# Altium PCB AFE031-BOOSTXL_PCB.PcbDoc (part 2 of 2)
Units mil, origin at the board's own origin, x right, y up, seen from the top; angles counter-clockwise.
Board outline 2300 x 2000 mil, 4 copper layers (Top Layer, POWER, GND, Bottom Layer), stack 61.6 mil thick; 92 components, 52 nets, 268 pads, 81 vias.
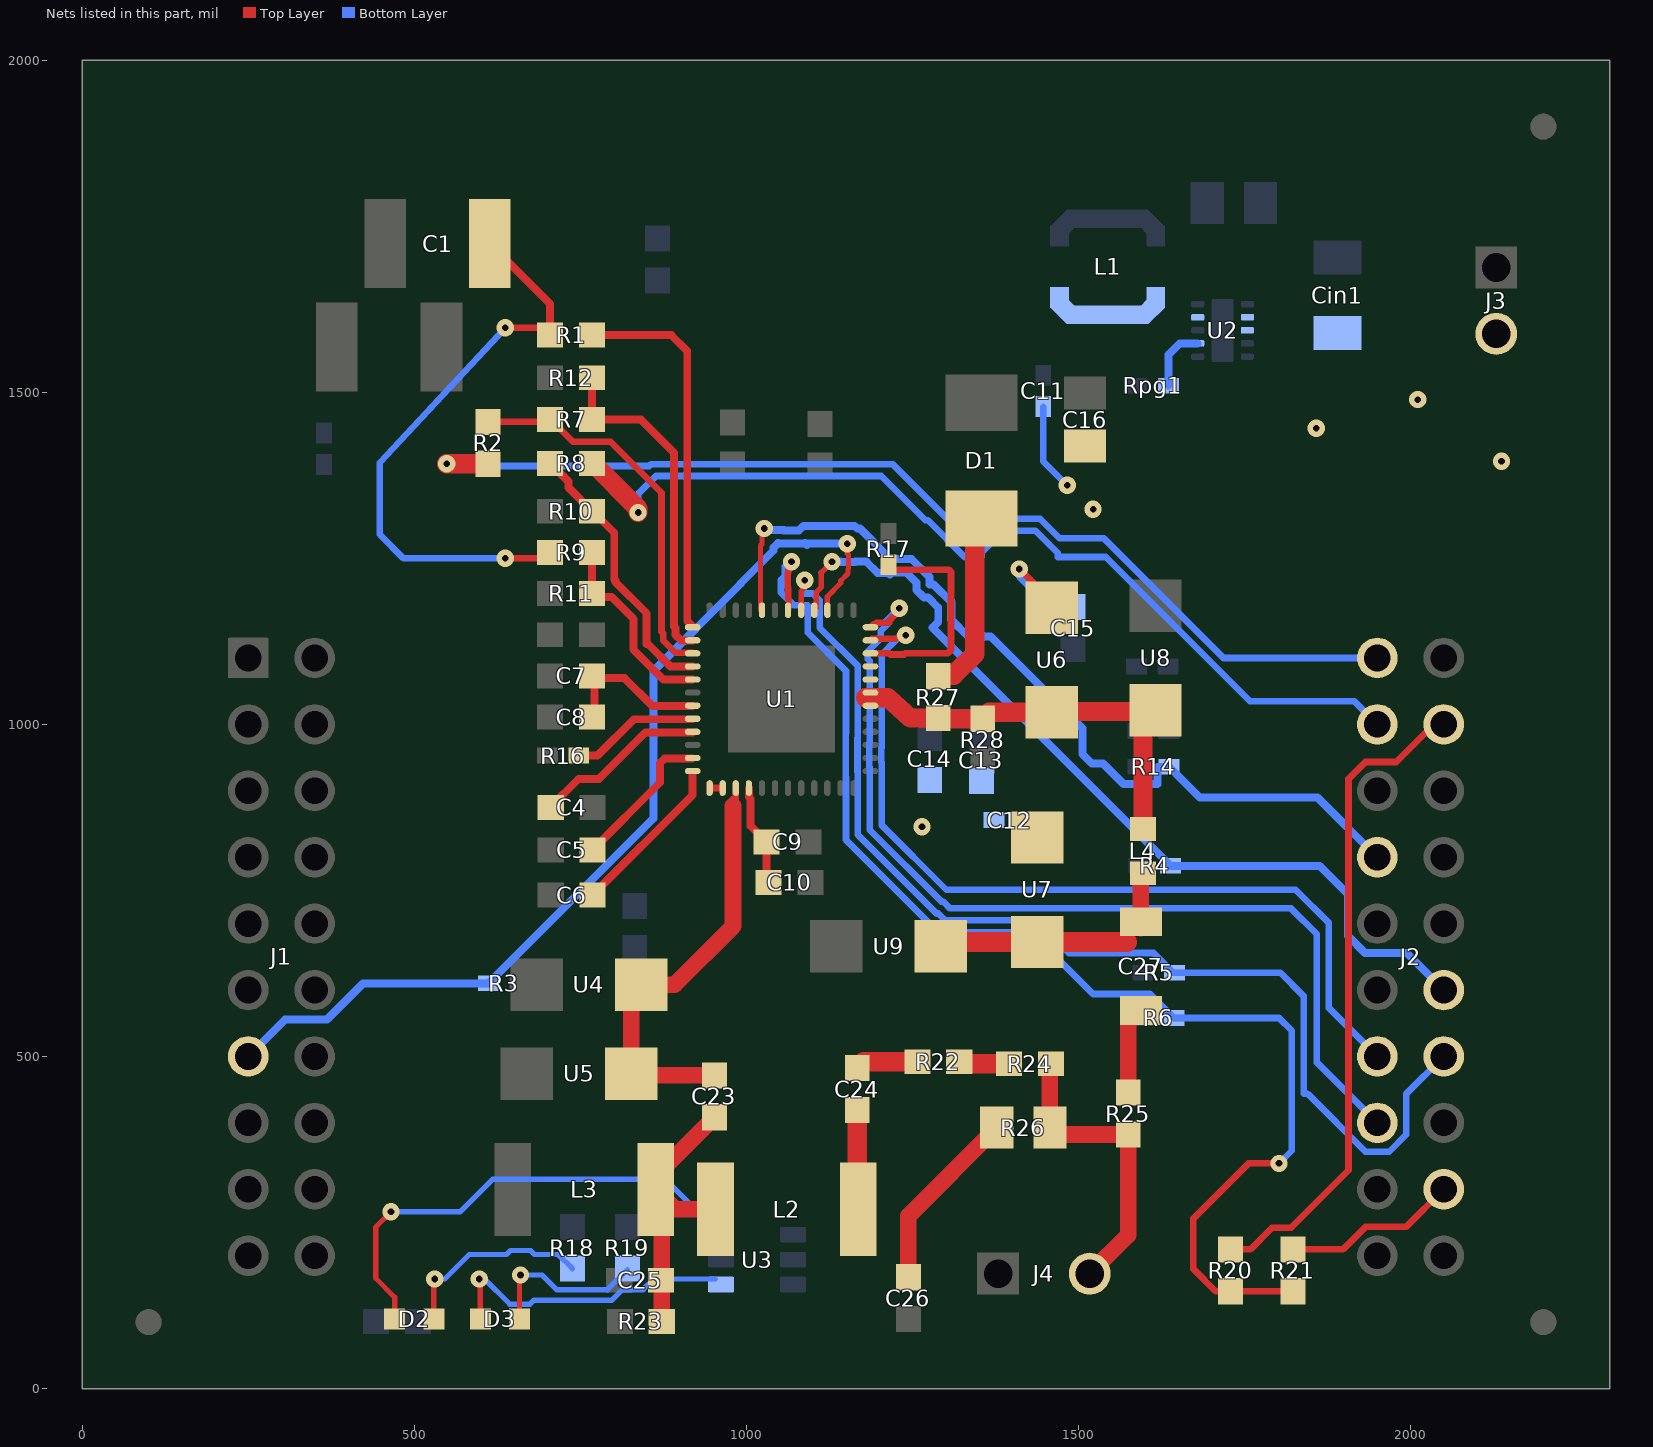
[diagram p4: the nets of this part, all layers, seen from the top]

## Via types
v1: diameter 26, hole 10, Top Layer to Bottom Layer, tented both sides, 66 vias
v2: diameter 20, hole 10, Top Layer to Bottom Layer, tented bottom, 12 vias
v3: diameter 22, hole 10, Top Layer to Bottom Layer, 3 vias

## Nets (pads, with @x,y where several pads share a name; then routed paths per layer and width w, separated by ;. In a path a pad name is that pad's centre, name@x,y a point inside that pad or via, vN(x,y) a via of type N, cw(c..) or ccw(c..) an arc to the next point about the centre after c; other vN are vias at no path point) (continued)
NetC4_2: C4.2 U1.21 | length 261.4
  Top Layer w12: C4.2@704.5,875 747.5,918 778,918 847.84,987.84 U1.21@919.14,987.84
NetC5_1: C5.1 U1.23 | length 223.8
  Top Layer w12: C5.1@768.5,811 869.7,912.2 869.7,941.3 876.72,948.33 U1.23@918.38,948.33
NetC6_1: C6.1 U1.24 | length 247.9
  Top Layer w12: C6.1@768.5,743 919.14,893.65 U1.24@919.14,928.46
NetC7_1: C7.1 C8.1 U1.19 | length 219.2
  Top Layer w12: C8.1@771.5,1016 771.5,1070 816.23,1070 858.63,1027.59 U1.19@919.14,1027.59
NetC9_1: C9.1 C10.1 U1.28 | length 135.2
  Top Layer w12: U1.28@1003.79,904.14 1003.79,890.44 1006.27,887.96 1006.27,847.24 C9.1@1030.5,823 C10.1@1030.5,780
NetC23_1: C23.1 C25.1 L2.1 L3.1 R23.2 | length 424.9
  Top Layer w25: L3.1@863.48,300 863.48,319.98 C23.1@952,408.5 ; R23.2@872.5,101 872.5,290.98 893.48,270 L2.1@953.52,270
NetC24_1: C24.1 R22.2 | length 81
  Top Layer w29: C24.1@1176.5,492 R22.2@1257.5,492
NetC24_2: C24.2 L2.2 | length 148
  Top Layer w29: L2.2@1167,271.48 C24.2@1167,419.5
NetC26_1: C26.1 R26.1 | length 280.6
  Top Layer w25: C26.1@1244,167.5 1244,260 R26.1@1377,393
NetC27_2: C27.2 L4.2 U7.2 U9.1 | length 362.5
  Top Layer w25: C27.2@1594,693.09 L4.2@1594,772.54
  Top Layer w29.53: U9.1@1292.74,666 1299,672.26 U7.2@1438,672.26 1573.17,672.26
NetD2_1: D2.1 U3.6 | length 734.1
  Top Layer w8: v1(465,266) 442,243 442,166 470.47,137.53 D2.1@470.47,105
  Bottom Layer w8: v1(465,266) 569,266 618,315 878.27,315 U3.6@961.87,231.4
NetD2_2: D2.2 R18.1 | length 294.6
  Top Layer w8: D2.2@529.53,105 v1@529.53,163.53
  Bottom Layer w8: v1(531,165) 545.85,165 582.73,201.87 638.73,201.87 644.73,207.87 675.27,207.87 681.27,201.87 716.63,201.87 R18.1@738,180.5
NetD3_1: D3.1 U3.4 | length 445.4
  Top Layer w8: D3.1@599.47,105 v1@599.47,163.53
  Bottom Layer w8: v1(598,165) 605.85,165 643.73,127.13 674.27,127.13 680.22,133.07 797.63,133.07 813.5,148.94 844.62,148.94 860.67,165 U3.4@953.46,165
NetD3_2: D3.2 R19.1 | length 241.1
  Top Layer w8: D3.2@658.53,105 v1@658.53,163.53
  Bottom Layer w8: v1(660,171) 692.33,171 699.33,164 714.38,148.94 791.06,148.94 R19.1@821,178.89
NetJ2_12: J2.12 R21.2 | length 264.5
  Top Layer w10: R21.2@1823,209.5 1898.14,209.5 1932.03,243.39 1993.39,243.39 J2.12@2050,300
NetJ2_19: J2.19 R20.2 | length 993.7
  Top Layer w10: R20.2@1729,209.5 1758.87,209.5 1791.43,242.06 1820.06,242.06 1906.61,328.61 1906.61,917.97 1932.03,943.39 1978.39,943.39 2035,1000 J2.19@2050,1000
NetL1_1: L1.1 U2.9
NetR1_1: R1.1 U1.13 | length 571.3
  Top Layer w12: R1.1@767.5,1586 887,1586 911,1562 911,1155.68 U1.13@919.14,1147.54
NetR2_1: R2.1 R7.1 U1.15 | length 586.1
  Top Layer w10: R2.1@611,1455.5 R7.1@702,1455.5 ; R7.1@705.5,1459 738.93,1425.57 795.51,1425.57 872.25,1348.84 872.25,1139.64 874.58,1137.3 874.58,1126.73 893.6,1107.71 U1.15@918.33,1107.71
  Top Layer w12: R7.1@705.5,1459 R7.1@705.5,1467.01
NetR8_1: R8.1 R10.2 U1.16 | length 425.9
  Top Layer w12: R8.1@704.5,1393 732,1365.5 732,1356.5 R10.2@767.5,1321 ; R10.2@769.5,1332.01 769.5,1320 801.06,1288.44 801.06,1218.45 803.06,1216.45 803.06,1214.05 849.87,1167.23 849.87,1120.67 852.11,1120.67 885.56,1087.21 U1.16@919.14,1087.21
NetR9_1: R9.1 R11.2 U1.17 | length 293.6
  Top Layer w12: R11.2@767.5,1194 R9.1@767.5,1259 ; R11.2@769.5,1192 797,1192 830,1159 830,1112.44 875.1,1067.34 U1.17@919.14,1067.34
NetR16_1: R16.1 U1.20 | length 182.2
  Top Layer w12: R16.1@759.62,953 776,953 830.72,1007.72 U1.20@919.14,1007.72
NetR17_2: R17.2 U1.46 | length 342.5
  Top Layer w10: U1.46@1186.86,1106.9 1214.93,1106.9 1216.7,1105.13 1237.3,1105.13 1239.07,1106.9 1302.9,1106.9 1308,1112 1308,1229.87 1304.87,1233 R17.2@1209.38,1233
NetRpg1_2: Rpg1.2 U2.7 | length 97.6
  Bottom Layer w12: Rpg1.2@1635.62,1510 1635.62,1556.62 1652.51,1573.51 U2.7@1679.6,1573.51
NetU1_25: U1.25 U1.26 | length 19.7
  Top Layer w10: U1.25@944.73,904.14 U1.26@964.42,904.14
PWM1: J2.40 R2.2 | length 1606.1
  Top Layer w29: v1(549,1392.5) R2.2@611,1392.5
  Bottom Layer w10: v1@552.5,1389 853.72,1389 856.6,1391.87 1220.13,1391.87 1332,1280 1350.05,1280 1379.68,1309.62 1442.32,1309.62 1471.95,1280 1538.28,1280 1718.28,1100 J2.40@1950,1100
PWM2: J2.39 R8.2 | length 1449.1
  Top Layer w29: R8.2@769,1393 837,1325 v1(837,1319)
  Bottom Layer w10: v1(837,1319) 837,1347 864,1374 1203,1374 1269.63,1307.37 1273.23,1307.37 1328.6,1252 1353.25,1252 1353.25,1257.92 1387.08,1291.75 1434.92,1291.75 1468.75,1257.92 1468.75,1252 1541,1252 1758,1035 1915,1035 J2.39@1950,1000
RX_FLAG: J2.33 U1.48 | length 1460.9
  Top Layer w10: U1.48@1186.86,1146.54 1191.09,1150.77 1193.32,1150.77 1195.53,1152.98 1214.81,1152.98 1214.81,1155.81 v1@1225,1166
  Bottom Layer w10: 1210,1155 v1(1230,1175) ; 1213.41,1151.59 1202.13,1140.3 1202.13,1129.13 1183,1110 1183,1098.09 1185.75,1095.34 1185.75,972.62 1185.25,972.12 1185.25,935.88 1185.75,935.38 1185.75,840.97 1293.6,733.13 1296.37,733.13 1306.5,723 1820,723 1859,684 1859,491 J2.33@1950,400
RXLINE: R22.1 R24.2 | length 72
  Top Layer w29: R22.1@1323.5,489 R24.2@1395.5,489
RXLINEF: C23.2 U1.27 U4.2 U5.1 | length 644
  Top Layer w10: 979.89,887.64 984.1,887.64 U1.27@984.1,904.14
  Top Layer w25: U5.1@826.74,474 U4.2@826.74,593 ; U5.1@829.24,471.5 C23.2@952,471.5 ; U4.2@860,626.26 U4.2@841.74,608 892,608 979.89,695.89 979.89,877.04
SD_EN: J2.37 R14.2 U1.8 | length 1339.8
  Top Layer w8: U1.8@1021.25,1171.86 1021.25,1254.64 1021.38,1254.76 1021.38,1269.27 1023.47,1271.37 1023.47,1291.47 v1(1027,1295)
  Bottom Layer w12: v1(1027,1295) v1@1028.74,1293.26 ; v1@1029.18,1292.82 1056.17,1292.82 1056.87,1292.13 1079.13,1292.13 1085.88,1298.87 1163.13,1298.87 1167.01,1295 1171,1295 1217.25,1248.75 1248.95,1248.75 1275.75,1221.95 1275.75,1210.75 1281.95,1210.75 1308.75,1183.95 1308.75,1157.25 1333.42,1132.58 1367.42,1132.58 1506.13,993.87 1506.13,955.11 1520.11,941.13 1537.07,941.13 1567.88,910.32 1619,910.32 1619,936 R14.2@1636.62,936 1682.62,890 1860,890 J2.37@1950,800
SPI_CLK: J1.7 R3.1 U1.3 | length 1471.6
  Top Layer w8: U1.3@1121.9,1171.86 1121.9,1192.66 1142.13,1212.89 1142.13,1216.3 1153,1227.18 1153,1233.82 1153.87,1234.7 1153.87,1255.3 1153,1256.18 1152,1257.18 v1(1152,1272)
  Bottom Layer w12: J1.7@250,500 305.61,555.61 368.39,555.61 422.77,610 R3.1@611.38,610 860,858.62 860,1080.24 990.87,1211.11 990.87,1211.87 1041.13,1262.13 1041.13,1266.13 1047.94,1272.95 1048.64,1272.25 1087.36,1272.25 1088.06,1272.95 1091.01,1270 1093.01,1272 v1(1152,1272)
SPI_CS: R6.1 R20.1 R21.1 U1.6 | length 1945.3
  Top Layer w8: U1.6@1064.03,1173.05 1064.03,1188.03
  Top Layer w10: 1064.03,1188.03 1063.13,1188.94 1063.13,1205.28 1062.13,1206.28 1062.13,1227.72 1063.13,1228.72 1063.13,1231.87 1068,1236.75 v1(1068,1245) ; v1(1802,339) 1756,339 1673,256 1673,180 1706.5,146.5 R20.1@1729,146.5 R21.1@1823,146.5
  Bottom Layer w10: v1@1059,1239 1058.13,1238.13 1058.13,1223.47 1052.13,1217.47 1052.13,1198.53 1071.53,1179.13 1092.6,1179.13 1092.6,1137.94 1150,1080.54 1150,987.42 1149.5,986.93 1149.5,921.07 1150,920.58 1150,826.17 1278.79,697.38 1281.57,697.38 1291.69,687.25 1428.75,687.25 1522,594 1607.62,594 R6.1@1643.62,558 1802,558 1821.13,538.87 1821.13,358.13 v1(1802,339)
SPI_SIMO: J2.15 R4.1 U1.4 | length 1345.4
  Top Layer w8: U1.4@1105.3,1174.94 1105.3,1199.12 1112.87,1206.7 1112.87,1227.3 1112.09,1228.09 v1(1129,1245)
  Bottom Layer w12: v1(1129,1245) 1141.41,1245 1142.28,1244.13 1163.72,1244.13 1164.59,1245 1180.62,1245 1197.75,1227.87 1214.13,1227.87 1216.21,1225.8 1219.28,1228.87 1240.72,1228.87 1255.87,1213.72 1255.87,1202.52 1267.52,1190.87 1273.72,1190.87 1288.87,1175.72 1288.87,1154.28 1280.11,1145.52 R4.1@1638.62,787 1863,787 1905.61,744.39 1905.61,681.61 1931.61,655.61 1994.39,655.61 J2.15@2050,600
SPI_SOMI: J2.14 R5.1 U1.5 | length 1730.6
  Top Layer w8: U1.5@1082.53,1171.86 1082.53,1200.47 1088,1205.95 v1(1088,1217)
  Bottom Layer w10: v1@1086,1213 1086,1197 1100,1197 1110.47,1186.53 1110.47,1145.34 1167.87,1087.94 1167.87,980.02 1167.38,979.52 1167.38,928.48 1167.87,927.98 1167.87,833.57 1286.19,715.25 1288.97,715.25 1299.1,705.13 1436.15,705.13 1485.4,655.87 1613.13,655.87 1618.32,650.68 1618.46,650.68 1626,643.14 1626,643 1643,626 R5.1@1644.62,626 1804,626 1839,591 1839,444 1844.64,444 1932.03,356.61 1967.97,356.61 1993.39,382.03 1993.39,443.39 J2.14@2050,500
TX_FLAG: J2.34 U1.47 | length 1310.4
  Top Layer w10: U1.47@1188.94,1128.67 1225.67,1128.67 1231,1134 v1(1240,1134)
  Bottom Layer w10: 1227,1128.72 1202.32,1104.05 1203.62,1102.75 1203.62,965.21 1203.13,964.72 1203.13,943.28 1203.62,942.79 1203.62,848.38 1301,751 1827,751 1877,701 1877,573 J2.34@1950,500
TX_PGA_IN: C1.1 R1.2 R9.2 | length 908.2
  Top Layer w10: v1(637,1250) 695.5,1250 R9.2@704.5,1259 ; v1(637,1597) 693.5,1597 R1.2@704.5,1586
  Top Layer w12: C1.1@613.74,1724 704.5,1633.24 R1.2@704.5,1586
  Bottom Layer w10: v1(637,1250) 484,1250 448,1286 448,1394 v1(637,1597)
TX_PGA_OUT: R7.2 R12.2 U1.14 | length 509.7
  Top Layer w12: R7.2@767.5,1460 R12.2@767.5,1522 ; R7.2@768.5,1459 841,1459 891.13,1408.87 891.13,1147.45 893.46,1145.12 893.46,1134.54 901.42,1126.58 U1.14@919.14,1126.58
TXLINE: C27.1 R25.2 | length 114.4
  Top Layer w25: R25.2@1575,445.5 C27.1@1575,559.91
TXLINEPF: L4.1 R27.1 R28.2 U1.42 U1.43 U6.2 U8.1 | length 594.3
  Top Layer w29: 1179.39,1040 1213,1040 1247.11,1009.5 R27.1@1289,1009.5 ; R27.1@1290.01,1008.5 R28.2@1356,1008.5 ; R28.2@1365.76,1018.26 U6.2@1460,1018.26 ; U6.2@1478,1019.26 U8.1@1616,1019.26 ; L4.1@1597,842.46 U8.1@1597,1017.26
TXRX: J4.2 R24.1 R25.1 R26.2 | length 435.6
  Top Layer w25: R26.2@1457,393 R24.1@1457,487.5 ; R26.2@1467.5,382.5 R25.1@1575,382.5 1575,231.1 J4.2@1516.9,173
VAFE: C11.1 C12.1 C13.1 C14.1 C15.2 C16.1 Cin1.1 D1.1 J3.2 R27.2 U1.44 U1.45 U2.2 U2.3 U6.1 U7.1 | length 586.6
  Top Layer w10: v1(1411,1234) 1460,1185 U6.1@1460,1175.74
  Top Layer w29.53: R27.2@1289,1072.5 1290.5,1074 1312,1074 1344,1106 D1.1@1344,1299.99
  Bottom Layer w10: v1(1411,1234) 1411,1222 1456.5,1176.5 C15.2@1492,1176.5 ; C11.1@1447,1478.38 1447,1396 v1(1483,1360)
  other v1: 1264.5,846 1522,1324 2137,1396 1858,1446 2011,1489
pads on no net: FID1.1 FID2.1 FID3.1 FID4.1 FID5.1 FID6.1 J1.2 J1.3 J1.4 J1.5 J1.6 J1.8 J1.9 J1.10 J1.21 J1.23 J1.24 J1.25 J1.26 J1.27 J1.28 J1.30 J2.11 J2.13 J2.16 J2.17 J2.31 J2.32 U1.10 U1.31 U1.32 U1.33 U1.36 U1.37 U2.11@1717,1568 U2.11@1717,1618.39

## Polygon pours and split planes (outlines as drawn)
GND on GND "GND" (solid, pour order 0): 0,0 2300,0 2300,2000 0,2000
VAFE on POWER "POWER-VAFE" (solid, remove dead copper, pour order 3): 0,0 2300,0 2300,2000 0,2000
3V3 on POWER "3V3" (solid, remove dead copper, pour order 2): 0,0 2300,0 2300,2000 0,2000
GND on Top Layer "Top Layer- GND" (solid, remove dead copper, pour order 5): 0,0 2300,0 2300,2000 0,2000
3V3 on Bottom Layer "Top Layer-No Net" (solid, remove dead copper, pour order 6): 0,0.49 2300,0.49 2300,2000.49 0,2000.49

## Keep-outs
Keep-Out Layer:
  text ".Layer_Name" at 577,-858.49 h60

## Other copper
Top Layer:
  rectangle net VAFE: 1463,1285 1553,1376
  rectangle net VAFE: 1373,1208 1499,1349
  rectangle net GND: 1193,1467 1300,1526
  rectangle net GND: 1370,1502 1408,1561
  rectangle net VAFE: 1384,1181 1430,1198
  rectangle net GND: 725,81 778,255
  rectangle net GND: 663,229 786,272
  rectangle net VAFE: 1210,792 1474,899
  rectangle net VAFE: 1176,1065 1304,1091
  rectangle net 3V3: 511,567 677,684
  rectangle net GND: 1318,105 1429,206
  rectangle net GND: 1226,84 1429,123
  rectangle net GND: 558,233 673,514
  rectangle net GND: 1560,1138 1754,1217
  rectangle net GND: 604,725 725,808
  rectangle net GND: 599,993 723,1091
  rectangle net GND: 1020,894 1026,959
  rectangle net GND: 1197,947 1340,965
  rectangle net GND: 1116,947 1197,1014
  rectangle net GND: 1117,856 1145,988
  rectangle net GND: 1073,627 1174,864
  rectangle net VAFE: 1382,1192 1438,1350
  rectangle net VAFE: 1333,1181 1408,1288
  rectangle net VAFE: 1464,1369 1555,1448
  text ".Layer_Name" at 577,-858.49 h60
POWER:
  rectangle net VAFE: 1299,1243 1901,1486
  rectangle net VAFE: 1313,1083 1457,1273
  rectangle net VAFE: 1300,890 1464,1291
  rectangle net VAFE: 1186,775 1463,922
  rectangle net VAFE: 1758.34,1311 2225,1635
Bottom Layer:
  rectangle net NetL1_1: 1455,1602 1621,1664
  rectangle net NetL1_1: 1606,1614 1657,1659
  rectangle net GND: 1670,1548 1714,1559
  rectangle net NetL1_1: 1566,1608 1689,1618
  rectangle net 3V3: 1668,1629 1692,1699
  rectangle net GND: 1714,1548 1763,1579
  rectangle net VAFE: 1743,1587 1824,1618
  rectangle net 3V3: 1331,1696 1720,1925
  rectangle net GND: 1700,1626 1779,1675
  rectangle net GND: 1747,1652 2163,1822
  rectangle net VAFE: 1805,1338 2223,1624
  rectangle net VAFE: 1246,833 1387,930
  rectangle net GND: 1747,1810 2123,1923
  text ".Layer_Name" at 577,-858.49 h60

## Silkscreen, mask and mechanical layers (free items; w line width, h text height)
Top Overlay:
  region: 2298.5,1100.5 2298.5,1146 2157.75,1146 2112,1100.25 2156.5,1055.25 2298.5,1055.25 2298.5,1100.5 2290.5,1100.5 2290.5,1063.25 2291,1062.75 2159.5,1062.75 2122.5,1100 2122.5,1101 2159.5,1138 2290.5,1138 2290.5,1100.5
  region: 599.75,1000.5 599.75,1046 459,1046 413.25,1000.25 457.75,955.25 599.75,955.25 599.75,1000.5 591.75,1000.5 591.75,963.25 592.25,962.75 460.75,962.75 423.75,1000 423.75,1001 460.75,1038 591.75,1038 591.75,1000.5
  region: 599.5,1101 599.5,1145.5 458,1145.5 413,1100.5 457.5,1055.5 599.5,1055.5 599.5,1101 560.5,1101 560.5,1075 480,1075 480,1127 560.5,1127 560.5,1101
  region: 0.5,1100 0.5,1055.5 142,1055.5 187,1100.5 142.5,1145.5 0.5,1145.5 0.5,1100 22,1100 22,1126 138,1126 138,1074 22,1074 22,1100
  text "GND" at 1932,1667 h72.83
  text "15V" at 1957,1557 h72.83
  text "BOOSTXL-AFE031" at 92,1220 h100 r90
  text "Rev E1" at 160,1220 h72.83 r90
  text "1" at 239,1167 h55
  text "21" at 323,1167 h55
  text "40" at 1925,1167 h55
  text "20" at 2024,1167 h55
  text "J1" at 133,1164 h72.83
  text "J3" at 405,1164 h72.83
  text "J4" at 1825,1164 h72.83
  text "J2" at 2104,1164 h72.83
  text "3V3" at 24,1078 h72.83
  text "5V" at 480.5,1078 h72.83
  text "PWM1" at 1693,1077 h72.83
  text "GND" at 2146.25,1075.75 h72.83
  text "GND" at 449.25,977 h72.83
  text "PWM2" at 1696,977 h72.83
  text "CS" at 2110,976 h72.83
  text "DAC_EN" at 1643,880 h72.83
  text "INT_EN" at 2110,877 h60
  text "SD_EN" at 1686,779 h72.83
  text "LED2" at 1729.3,675 h72.83
  text "MOSI" at 2110,577 h72.83
  text "LED1" at 1728.96,575 h72.83
  text "TX_Flag" at 1647,483 h72.83
  text "CLK" at 67.03,477 h72.83
  text "MISO" at 2110,477 h72.83
  text "RX_Flag" at 1646,374 h72.83
  text "ADCIN" at 396,284 h50
  text "CS" at 2110,277 h72.83
  text "31" at 1928,98 h55
  text "11" at 2027,98 h55
  text "10" at 227,97 h55
  text "30" at 325,97 h55
  text "CS Jumpers" at 1661,78 h50
  text ".Layer_Name" at 577,-858.49 h60
Bottom Overlay:
  drawing of 3638 lines, arcs and shapes, not listed
  text "AFE031 BoosterPack" at 1720,1351.32 h72.83
  text "BOOSTXL-AFE031" at 1720,1294.22 h72.83
  text "Rev E1" at 1720,1226.36 h60
  text "1" at 297,1160 h55
  text "21" at 397.5,1160 h55
  text "40" at 1999,1160 h55
  text "20" at 2097.5,1160 h55
  text "J4" at 1902.5,1158 h72.83
  text "J1" at 202.5,1154 h72.83
  text "J3" at 479,1154 h72.83
  text "J2" at 2179,1153.5 h72.83
  text "3V3" at 133.5,1077.5 h72.83
  text "GND" at 2287,1077.5 h72.83
  text "5V" at 553,1077 h72.83
  text "PWM1" at 1902,1046 h50
  text "GND" at 588,977.5 h72.83
  text "CS" at 2280,948 h50
  text "PWM2" at 1902.5,945 h50
  text "DAC_EN" at 1902.5,851 h50
  text "INT_EN" at 2302,847 h50
  text "SD_EN" at 1902.5,745 h50
  text "LED2" at 1903.5,652 h50
  text "MOSI" at 2279,553 h50
  text "LED1" at 1902.5,545 h50
  text "TX_Flag" at 1902.5,452 h50
  text "MISO" at 2280,447 h50
  text "CLK" at 202.5,445 h72.83
  text "RX_Flag" at 1902.5,345 h50
  text "ADCIN" at 556,255 h50
  text "CS" at 2283,247 h50
  text "31" at 1999,92 h55
  text "11" at 2097.5,92 h55
  text "10" at 300,89 h55
  text "30" at 400,89 h55
  text ".Layer_Name" at 577,-858.49 h60
Top Paste:
  text ".Layer_Name" at 577,-858.49 h60
Bottom Paste:
  text ".Layer_Name" at 577,-858.49 h60
Top Solder:
  text ".Layer_Name" at 577,-858.49 h60
  text ".Layer_Name" at 577,-858.49 h60
Bottom Solder:
  text ".Layer_Name" at 577,-858.49 h60
Drill Guide:
  text ".Layer_Name" at 577,-858.49 h60
M1 Board Outline:
  the board outline again, w10
  text ".Layer_Name" at 577,-858.49 h60
M2 Board Dimensions:
  rectangle: 0,-275 125,-150
  rectangle: 125,-400 500,-275
  lines w7: 0,-275 1000,-275 ; 125,-400 125,-150 ; 250,-400 250,-150 ; 500,-400 500,-150 ; 750,-400 750,-150 ; 0,-400 1000,-400 1000,-150 0,-150 0,-400
  text ".Layer_Name" at 577,-858.49 h60
M3 3D STEP Top:
  text ".Layer_Name" at 577,-858.49 h60
M4 3D STEP Bottom:
  text ".Layer_Name" at 577,-858.49 h60
M5 Assembly Top:
  lines w10: -292,-930.17 6308,-930.17 ; -292,-726.83 6310,-726.83 ; -292,-523.5 -292,-1133.5 3713,-1133.5 6310,-1133.5 6310,-523.5 -291.5,-523.5 -291.5,-1133.5 1284,-1133.5 ; 2173,-1133.5 2173,-523.5 ; 3440,-726.83 3440,-523.5 ; 4280,-726.83 4280,-523.5 ; 4902,-1140 4902,-937.17
  text "COMPONENTS MARKED 'DNP' SHOULD NOT BE POPULATED." at 1153.5,-318.5 h60
  text "ASSEMBLY VARIANT:" at 1153,-434 h60
  text ".VariantName" at 2189,-434 h60
  text "PCB VIEWED FROM TOP SIDE" at -228.5,-655.67 h60
  text "BOARD #:" at 2248,-655.67 h60
  text ".PRJ_Number" at 2793.5,-655.67 h60
  text "REV:" at 3638,-655.67 h60
  text ".PCB_Rev" at 3929.5,-655.67 h60
  text "SVN REV:" at 4476,-655.67 h60
  text ".VersionControl_RevNumber" at 4982,-655.67 h60
  text "TID #:" at 2248,-859 h60
  text ".TID" at 2793.5,-859 h60
  text "PLOT NAME =" at -228.5,-1064.34 h60
  text ".plot_File_Name" at 577,-1064.34 h60
  text "GENERATED    :" at 2250,-1064.34 h60
  text ".Print_Date" at 3119.5,-1064.34 h60
  text ".Print_Time" at 3848.5,-1064.34 h60
  text "TEXAS INSTRUMENTS" at 5113,-1064.34 h60
M6 Assembly Bottom:
  lines w10: -292.5,-727.33 6309.5,-727.33 ; -290.5,-930.67 6309.5,-930.67 ; 1115.5,-1140.5 1115.5,-937.67 ; 1737.5,-727.33 1737.5,-524 ; 2577.5,-727.33 2577.5,-524 ; 3844.5,-1134 3844.5,-524 ; 4733.5,-1134 6309,-1134 6309,-524 -292.5,-524 -292.5,-1134 2304.5,-1134 6309.5,-1134 6309.5,-524
  text "COMPONENTS MARKED 'DNP' SHOULD NOT BE POPULATED." at 6102,-318 h60
  text ".VariantName" at 5058,-434 h60
  text "ASSEMBLY VARIANT:" at 6097,-434 h60
  text ".VersionControl_RevNumber" at 1035.5,-656.17 h60
  text "SVN REV:" at 1541.5,-656.17 h60
  text ".PCB_Rev" at 2088,-656.17 h60
  text "REV:" at 2379.5,-656.17 h60
  text ".PRJ_Number" at 3224,-656.17 h60
  text "BOARD #:" at 3769.5,-656.17 h60
  text "PCB VIEWED FROM BOTTOM SIDE" at 6246,-656.17 h60
  text ".TID" at 3224,-859.5 h60
  text "TID #:" at 3769.5,-859.5 h60
  text "TEXAS INSTRUMENTS" at 904.5,-1064.84 h60
  text ".Print_Time" at 2169,-1064.84 h60
  text ".Print_Date" at 2898,-1064.84 h60
  text "GENERATED    :" at 3767.5,-1064.84 h60
  text ".plot_File_Name" at 5440.5,-1064.84 h60
  text "PLOT NAME =" at 6246,-1064.84 h60
M9 Title Sheet:
  drawing of 57 lines, arcs and shapes, not listed
  text "1" at 739.84,8036.5 h70
  text "2" at 3235.5,8036.5 h70
  text "3" at 5724.84,8036.5 h70
  text "4" at 8231.51,8036.5 h70
  text "5" at 10730.5,8036.5 h70
  text "6" at 13235.5,8036.5 h70
  text "A" at -416.5,6893.5 h70
  text "A" at 14383.5,6893.5 h70
  text "B" at -416.5,4513.5 h70
  text "B" at 14383.5,4513.5 h70
  text "C" at -416.5,2138.5 h70
  text "C" at 14383.5,2138.5 h70
  text "PROJECT TITLE:" at 11343.5,277.5 h45
  text ".PRJ_Title" at 11393.5,144.17 h70
  text "DESIGNED FOR:" at 11343.5,-23.5 h45
  text ".PRJ_Customer" at 11393.5,-163.5 h70
  text "D" at -416.5,-231.5 h70
  text "D" at 14383.5,-231.5 h70
  text "FILE NAME:" at 11343.5,-323.5 h45
  text ".PCB_File_Name_No_Path" at 11393.5,-443.5 h70
  text "Texas Instruments (TI) and/or its licensors do not warrant the accuracy or completeness of this specification" at 6374,-605.34 h45
  text "ENGINEER:" at 11343.5,-613.5 h45
  text "LAYOUT BY:" at 12848.5,-613.5 h45
  text "or any information contained therein. TI and/or its licensors do not warrant that this design will meet" at 6329.01,-718 h45
  text ".PRJ_Engineer" at 11393.5,-768.49 h70
  text ".PCB_Layout" at 12899,-768.49 h70
  text "the specifications, will be suitable for your application or fit for any particular purpose, or will operate in" at 6329.01,-830.67 h45
  text ".Layer_Name" at 577,-858.49 h60
  text "ALTIUM DESIGNER VERSION:" at 12848.5,-923.5 h45
  text "an implementation. TI and/or its licensors do not warrant that the design is production worthy. You should" at 6329.01,-943.33 h45
  text "completely validate and test your design implementation to confirm the system functionality for your application." at 6374,-1056 h45
  text ".print_Scale" at 11393.5,-1056.83 h70
  text ".Application_BuildNumber" at 12899,-1056.83 h70
  text "1" at 739.84,-1263.5 h70
  text "2" at 3235.5,-1263.5 h70
  text "3" at 5724.84,-1263.5 h70
  text "4" at 8231.51,-1263.5 h70
  text "5" at 10730.5,-1263.5 h70
  text "6" at 13235.5,-1263.5 h70
M10 Fab Notes:
  drawing of 173 lines, arcs and shapes, not listed
  text "DESIGN INFORMATION" at 12378.02,6201 h60
  text "MIN. TRACK WIDTH:" at 11733.46,6021 h60
  text "8" at 12829.7,6021 h60
  text "MIL" at 12984.46,6021 h60
  text "MIN. CLEARANCE:" at 11733.46,5889 h60
  text "0.2" at 12769.7,5889 h60
  text "mm" at 12984.46,5889 h60
  text "MIN. VIA PAD SIZE:" at 11733.46,5757 h60
  text "24" at 12799.71,5757 h60
  text "MIL" at 12984.46,5757 h60
  text "0.05mm (2MIL)" at 12428.46,5615.29 h60
  text "MINIMUM ANNULAR RING" at 11404.23,5611 h60
  text "EXTERNAL" at 13136.46,5611 h60
  text "PER" at 11604.23,5493 h60
  text "IPC-D-275 CLASS 2 LEVEL C" at 11824.23,5493 h60
  text "MIL, HOLES" at 13312.46,5380.71 h60
  text "+/-" at 12920,5380 h60
  text "+/-" at 13774,5380 h60
  text "REGISTRATION TOLERANCES:" at 11404.23,5375 h60
  text "METAL" at 12604,5375 h60
  text "5" at 13180.2,5375 h60
  text "3" at 14013.2,5375 h60
  text "MIL" at 14129.46,5375 h60
  text "+/-" at 13774,5262 h60
  text "HOLE SIZE TOLERANCE (UNLESS OTHERWISE SPECIFIED):" at 11404.23,5257 h60
  text "3" at 14013.2,5257 h60
  text "MIL" at 14129.46,5257 h60
  text "MATERIAL:" at 11329.46,5047.54 h60
  text "FR-4 High Tg" at 12315.9,4907.21 h60
  text "FR-408" at 11750.46,4898.64 h60
  text "OTHER" at 13238.46,4898.64 h60
  text "X" at 12161,4895 h60
  text "62 MIL (1.6mm) +/-10%" at 12070.56,4735.92 h60
  text "THICKNESS:" at 11404.23,4731.64 h60
  text "X" at 11942.4,4731.64 h60
  text "OTHER" at 13355.46,4731.64 h60
  text "TOLERANCE:" at 11404.23,4573.64 h60
  text "X" at 12243.53,4573.64 h60
  text "ANSI IPC-6012 TYPE 3 CLASS 2" at 12430.48,4573.64 h60
  text "OTHER +/-" at 12430.46,4417.64 h60
  text "BOW & TWIST:" at 11404.23,4260.64 h60
  text "X" at 12243.53,4260.64 h60
  text "ANSI IPC-6012 TYPE 3 CLASS 2" at 12430.48,4260.64 h60
  text "OTHER +/-" at 12430.46,4102.13 h60
  text "DRILLING:" at 11329.46,3963.64 h60
  text "REFERENCE:" at 11404.23,3846.64 h60
  text "X" at 12052.46,3846.64 h60
  text "AS SHOWN" at 12239.46,3846.64 h60
  text "X" at 12953.46,3846.64 h60
  text "NC_DRILL FILES" at 13090.46,3846.64 h60
  text "PTH COPPER THICKNESS:" at 11404.23,3688.64 h60
  text "X" at 12534.46,3688.64 h60
  text "20-30 um" at 12671.46,3688.64 h60
  text "OTHER" at 13388.46,3688.64 h60
  text "BOARD FINISH:" at 11329.46,3529.64 h60
  text "SILKSCREEN:" at 11484.68,3411.64 h60
  text "X" at 12433.46,3411.64 h60
  text "TOP" at 12559.46,3411.64 h60
  text "X" at 12943.46,3411.64 h60
  text "BOTTOM" at 13070.46,3411.64 h60
  text "SILKSCREEN COLOR:" at 11484.68,3244.64 h60
  text "X" at 12432.42,3244.64 h60
  text "WHITE" at 12559.46,3244.64 h60
  text "OTHER" at 13070.46,3244.64 h60
  text "RED" at 13677.46,3094.44 h60
  text "GREEN" at 12690.46,3085.44 h60
  text "OTHER" at 13308.46,3085.44 h60
  text "X" at 13158,3084 h60
  text "SOLDER RESIST COLOR:" at 11484.68,3074.64 h60
  text "X" at 12563.42,2915.44 h60
  text "MATTE" at 12690.46,2915.44 h60
  text "SEMI-GLOSS" at 13308,2914.8 h60
  text "IMMERSION GOLD (ENIG)" at 12390.46,2726.92 h60
  text "ENEPIG" at 13728,2723.64 h60
  text "SURFACE FINISH:" at 11329.46,2722.64 h60
  text "X" at 12203.51,2722.64 h60
  text "IMM. TIN/SILVER OR EQUIV" at 11659,2565.64 h60
  text "OTHER" at 13090.46,2565.64 h60
  text "ARRAY/PANEL:" at 11329.46,2386.64 h60
  text "CUT AND TRIM PER M1 BOARD OUTLINE" at 12390.46,2382.35 h60
  text "N.C. ROUTE" at 12390.46,2230.64 h60
  text "X" at 13069.46,2230.64 h60
  text "V. SCORE" at 13256.46,2230.64 h60
  text "CERTIFICATION:" at 11329.46,2093.64 h60
  text "MATERIALS AND WORKMANSHIP FOR ALL PCBS" at 12054.46,2093.64 h60
  text "TO MEET OR EXCEED THE REQUIREMENTS OF:" at 12054.46,1995.64 h60
  text "X" at 11680.96,1859.13 h60
  text "ANSI IPC-A-600F CLASS ->" at 11819.96,1859.13 h60
  text "X" at 13459.02,1859.13 h60
  text "2" at 13577.96,1859.14 h60
  text "1" at 13262.96,1857.64 h60
  text "3" at 13931.96,1857.64 h60
  text "X" at 12495.02,1699.64 h60
  text "RoHS" at 12631.96,1699.64 h60
  text "OTHER" at 13276.36,1699.64 h60
  text "PER ORDER" at 13673.42,1699.64 h60
  text "ALL BOARDS MUST MEET OR EXCEED UL94-V0 REQUIREMENTS." at 11357,1534 h60
  text "PCB MUST BEAR THE UL94V-0 UL REGISTERED MATERIAL ID NUMBER" at 11357,1414 h60
  text "ADDITIONAL REQUIREMENTS:" at 11329.46,1240.64 h60
  text "MICROSECTION:" at 11404.23,1125.64 h60
  text "YES" at 12309.96,1125.64 h60
  text "REQUIRED" at 13171.46,969.49 h60
  text "BARE BOARD ELEC. TEST:" at 11404.23,966.64 h60
  text "NONE" at 12709.96,966.64 h60
  text "X" at 13044.46,966.64 h60
  text "PER ORDER" at 13763.46,966.64 h60
  text ".Layer_Name" at 577,-858.49 h60
M11 Gerber Information:
  lines w10: -292,-930.17 6308,-930.17 ; -292,-726.83 6310,-726.83 ; -292,-523.5 -292,-1133.5 3713,-1133.5 6310,-1133.5 6310,-523.5 -291.5,-523.5 -291.5,-1133.5 1284,-1133.5 ; 2173,-1133.5 2173,-523.5 ; 3440,-726.83 3440,-523.5 ; 4280,-726.83 4280,-523.5 ; 4902,-1140 4902,-937.17
  text "ALL ARTWORK VIEWED FROM TOP SIDE" at -228.5,-655.67 h60
  text "BOARD #:" at 2248,-655.67 h60
  text ".PRJ_Number" at 2793.5,-655.67 h60
  text "REV:" at 3638,-655.67 h60
  text ".PCB_Rev" at 3929.5,-655.67 h60
  text "SVN REV:" at 4476,-655.67 h60
  text ".VersionControl_RevNumber" at 4982,-655.67 h60
  text "LAYER NAME =" at -228.5,-858.49 h60
  text "TID #:" at 2248,-859 h60
  text ".TID" at 2793.5,-859 h60
  text "PLOT NAME =" at -228.5,-1064.34 h60
  text ".plot_File_Name" at 577,-1064.34 h60
  text "GENERATED    :" at 2250,-1064.34 h60
  text ".Print_Date" at 3119.5,-1064.34 h60
  text ".Print_Time" at 3848.5,-1064.34 h60
  text "TEXAS INSTRUMENTS" at 5113,-1064.34 h60
M12 Stackup:
  drawing of 295 lines, arcs and shapes, not listed
  text "Layer" at 5133.58,6294 h60
  text "Name" at 5543.49,6294 h60
  text "Material" at 6473.23,6294 h60
  text "Thickness" at 7333,6294 h60
  text "Constant" at 7982.84,6294 h60
  text "Board Layer Stack" at 8552.7,6294 h60
  text "1" at 5133.58,6174 h60
  text "Top Overlay" at 5543.49,6174 h60
  text "2" at 5133.58,6054 h60
  text "Top Solder" at 5543.49,6054 h60
  text "Solder Resist" at 6473.23,6054 h60
  text "0.40mil" at 7333,6054 h60
  text "3.5" at 7982.84,6054 h60
  text "3" at 5133.58,5934 h60
  text "Top Layer" at 5543.49,5934 h60
  text "Copper" at 6473.23,5934 h60
  text "1.40mil" at 7333,5934 h60
  text "4" at 5133.58,5814 h60
  text "Dielectric1" at 5543.49,5814 h60
  text "FR-4" at 6473.23,5814 h60
  text "8.00mil" at 7333,5814 h60
  text "4.2" at 7982.84,5814 h60
  text "5" at 5133.58,5694 h60
  text "POWER" at 5543.49,5694 h60
  text "Copper" at 6473.23,5694 h60
  text "1.40mil" at 7333,5694 h60
  text "6" at 5133.58,5574 h60
  text "Dielectric 2" at 5543.49,5574 h60
  text "FR-4" at 6473.23,5574 h60
  text "40.00mil" at 7333,5574 h60
  text "4.2" at 7982.84,5574 h60
  text "7" at 5133.58,5454 h60
  text "GND" at 5543.49,5454 h60
  text "Copper" at 6473.23,5454 h60
  text "1.40mil" at 7333,5454 h60
  text "8" at 5133.58,5334 h60
  text "Dielectric 3" at 5543.49,5334 h60
  text "FR-4" at 6473.23,5334 h60
  text "8.00mil" at 7333,5334 h60
  text "4.2" at 7982.84,5334 h60
  text "9" at 5133.58,5214 h60
  text "Bottom Layer" at 5543.49,5214 h60
  text "Copper" at 6473.23,5214 h60
  text "1.40mil" at 7333,5214 h60
  text "10" at 5133.58,5094 h60
  text "Bottom Solder" at 5543.49,5094 h60
  text "Solder Resist" at 6473.23,5094 h60
  text "0.40mil" at 7333,5094 h60
  text "3.5" at 7982.84,5094 h60
  text "11" at 5133.58,4974 h60
  text "Bottom Overlay" at 5543.49,4974 h60
  text ".Layer_Name" at 577,-858.49 h60
M13 Component Bodies Top:
  text ".Layer_Name" at 577,-858.49 h60
M14 Component Bodies Bottom:
  text ".Layer_Name" at 577,-858.49 h60
M15 Courtyards Top:
  text ".Layer_Name" at 577,-858.49 h60
M16 Courtyards Bottom:
  text ".Layer_Name" at 577,-858.49 h60
Drill Drawing:
  lines w10: 5336.09,3045.27 5391.34,3045.27 5363.72,2990.02 5336.09,3045.27 ; 5336.09,3114.34 5391.34,3114.34 5391.34,3169.59 5336.09,3169.59 5336.09,3114.34 ; 5336.09,3238.66 5363.72,3252.47 5391.34,3238.66 5377.53,3266.28 5391.34,3293.91 5363.72,3280.1 5336.09,3293.91 5349.9,3266.28 5336.09,3238.66
  lines w12: 5286,2952.72 8517.49,2952.72 ; 5286,3325.68 8517.49,3325.68 ; 5623.86,2828.4 5623.86,3450 ; 5955.86,2828.4 5955.86,3450 ; 6592.43,2828.4 6592.43,3450 ; 6851.57,2828.4 6851.57,3450 ; 7226.72,2828.4 7226.72,3450 ; 7951.05,2828.4 7951.05,3450 ; 5286,2828.4 8517.49,2828.4 8517.49,3450 5286,3450 5286,2828.4
  text "Symbol" at 5360.59,3362.98 h72
  text "Quantity" at 5661.16,3362.98 h72
  text "Finished Hole Size" at 5993.16,3362.98 h72
  text "Plated" at 6629.72,3362.98 h72
  text "Hole Type" at 6888.86,3362.98 h72
  text "Drill Layer Pair" at 7264.02,3362.98 h72
  text "Hole Tolerance" at 7988.35,3362.98 h72
  text "81" at 5661.16,3238.66 h60
  text "10.00mil (0.254mm)" at 5993.16,3238.66 h60
  text "PTH" at 6629.72,3238.66 h60
  text "Round" at 6888.86,3238.66 h60
  text "Top Layer - Bottom Layer" at 7264.02,3238.66 h60
  text "40" at 5661.16,3114.34 h60
  text "40.16mil (1.020mm)" at 5993.16,3114.34 h60
  text "PTH" at 6629.72,3114.34 h60
  text "Round" at 6888.86,3114.34 h60
  text "Top Layer - Bottom Layer" at 7264.02,3114.34 h60
  text "4" at 5661.16,2990.02 h60
  text "43.31mil (1.100mm)" at 5993.16,2990.02 h60
  text "PTH" at 6629.72,2990.02 h60
  text "Round" at 6888.86,2990.02 h60
  text "Top Layer - Bottom Layer" at 7264.02,2990.02 h60
  text "125 Total" at 5661.16,2865.7 h60
  text ".Layer_Name" at 577,-858.49 h60
M17 Embedded Cavity:
  text ".Layer_Name" at 577,-858.49 h60
M18 Embedded Assembly:
  text ".Layer_Name" at 577,-858.49 h60
M19 Embedded Keepout:
  text ".Layer_Name" at 577,-858.49 h60

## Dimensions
0,-400 to 1000,-400 on M2 Board Dimensions
0,0 to 0,2000 on M2 Board Dimensions
0,0 to 2300,0 on M2 Board Dimensions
